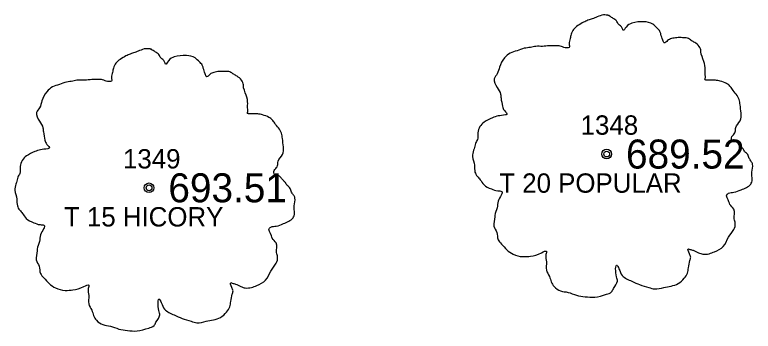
# Model space of a CAD drawing. Extents: x 1655137 to 1657928, y 1003994 to 1005407.
# Drawn here: x 1655879.78 to 1655917.99, y 1004697.34 to 1004713.71 of the extents above; entities that cross this region are included whole.
import ezdxf

# ---------------------------------------------------------------- set-up
doc = ezdxf.new("R2010")
doc.units = 0
for name, color, linetype in [('RD_EX_TX_VEG_ELEV', 7, 'Continuous'), ('RD_EX_VEG', 7, 'Continuous'), ('RD_EX_VEG_txCode', 7, 'Continuous'), ('RD_SMD_Locator', 7, 'Continuous')]:
    doc.layers.add(name, color=color, linetype=linetype)

msp = doc.modelspace()

# ---------------------------------------------------------------- linework, layer by layer
at = {"layer": 'RD_EX_VEG'}
for centre, radius in [((1655910.407, 1004706.504), 0.25), ((1655910.394, 1004706.486), 0.0001), ((1655886.725, 1004704.759), 0.25), ((1655886.712, 1004704.74), 0.0001)]:
    msp.add_circle(centre, radius, dxfattribs=at)
for points in [[(1655910.539, 1004713.672), (1655910.239, 1004713.697), (1655909.914, 1004713.597), (1655909.664, 1004713.497), (1655909.439, 1004713.422), (1655909.214, 1004713.322), (1655908.914, 1004713.147), (1655908.689, 1004712.947), (1655908.564, 1004712.697), (1655908.514, 1004712.472), (1655908.464, 1004712.197), (1655908.464, 1004712.022), (1655908.34, 1004711.997), (1655908.19, 1004712.022), (1655907.94, 1004712.097), (1655907.69, 1004712.097), (1655907.44, 1004712.097), (1655907.09, 1004712.072), (1655906.74, 1004712.072), (1655906.465, 1004712.022), (1655906.14, 1004711.972), (1655905.766, 1004711.847), (1655905.416, 1004711.722), (1655905.116, 1004711.473), (1655904.866, 1004710.998), (1655904.741, 1004710.648), (1655904.591, 1004710.398), (1655904.741, 1004709.948), (1655904.916, 1004709.598), (1655904.941, 1004709.398), (1655905.016, 1004708.974), (1655905.116, 1004708.749), (1655905.241, 1004708.549), (1655905.166, 1004708.524), (1655904.791, 1004708.474), (1655904.491, 1004708.374), (1655904.066, 1004708.149), (1655903.841, 1004707.924), (1655903.741, 1004707.599), (1655903.717, 1004707.249), (1655903.617, 1004707.05), (1655903.542, 1004706.775), (1655903.517, 1004706.7), (1655903.467, 1004706.375), (1655903.567, 1004705.925), (1655903.592, 1004705.575), (1655903.717, 1004705.35), (1655903.866, 1004705.175), (1655904.041, 1004704.925), (1655904.441, 1004704.701), (1655904.766, 1004704.601), (1655904.966, 1004704.576), (1655904.791, 1004704.076), (1655904.741, 1004703.726), (1655904.616, 1004703.326), (1655904.616, 1004703.251), (1655904.566, 1004702.776), (1655904.716, 1004702.451), (1655904.791, 1004702.077), (1655904.966, 1004701.852), (1655905.241, 1004701.552), (1655905.566, 1004701.327), (1655906.066, 1004701.202), (1655906.465, 1004701.227), (1655907.04, 1004701.402), (1655907.29, 1004701.477), (1655907.265, 1004701.302), (1655907.29, 1004700.927), (1655907.29, 1004700.502), (1655907.44, 1004700.178), (1655907.54, 1004699.903), (1655907.69, 1004699.653), (1655908.015, 1004699.428), (1655908.414, 1004699.353), (1655908.839, 1004699.203), (1655909.289, 1004699.128), (1655909.789, 1004699.103), (1655910.389, 1004699.253), (1655910.663, 1004699.378), (1655910.763, 1004699.553), (1655910.963, 1004699.928), (1655910.913, 1004700.153), (1655910.938, 1004700.752), (1655911.038, 1004700.577), (1655911.213, 1004700.227), (1655911.713, 1004699.928), (1655912.113, 1004699.753), (1655912.588, 1004699.603), (1655912.888, 1004699.528), (1655913.362, 1004699.603), (1655913.737, 1004699.678), (1655914.112, 1004699.803), (1655914.412, 1004700.078), (1655914.587, 1004700.352), (1655914.637, 1004700.627), (1655914.712, 1004701.002), (1655914.762, 1004701.177)], [(1655914.762, 1004701.177), (1655914.687, 1004701.352), (1655914.637, 1004701.602), (1655914.712, 1004701.577), (1655914.887, 1004701.527), (1655915.162, 1004701.402), (1655915.386, 1004701.327), (1655915.711, 1004701.352), (1655915.986, 1004701.452), (1655916.436, 1004701.727), (1655916.711, 1004702.202), (1655916.986, 1004702.601), (1655917.061, 1004702.926), (1655917.011, 1004703.151), (1655916.986, 1004703.651), (1655916.786, 1004703.901), (1655916.736, 1004704.026), (1655916.636, 1004704.426), (1655916.711, 1004704.476), (1655916.986, 1004704.526), (1655917.361, 1004704.651), (1655917.635, 1004704.775), (1655917.86, 1004704.95), (1655917.935, 1004705.175), (1655917.91, 1004705.575), (1655917.96, 1004705.975), (1655917.885, 1004706.125), (1655917.785, 1004706.275), (1655917.71, 1004706.475), (1655917.56, 1004706.625), (1655917.461, 1004706.775), (1655917.361, 1004706.875), (1655917.236, 1004707.025), (1655917.061, 1004707.149), (1655916.911, 1004707.199), (1655916.861, 1004707.349), (1655917.011, 1004707.549), (1655917.061, 1004707.649), (1655917.086, 1004707.874), (1655917.311, 1004708.224), (1655917.361, 1004708.624), (1655917.311, 1004709.049), (1655917.261, 1004709.324), (1655917.111, 1004709.598), (1655916.911, 1004709.848), (1655916.786, 1004710.023), (1655916.611, 1004710.148), (1655916.286, 1004710.273), (1655916.036, 1004710.323), (1655915.686, 1004710.323), (1655915.486, 1004710.373), (1655915.511, 1004710.423), (1655915.511, 1004710.573), (1655915.511, 1004710.848), (1655915.436, 1004711.298), (1655915.286, 1004711.797), (1655915.286, 1004711.822), (1655915.186, 1004712.072), (1655914.962, 1004712.272), (1655914.787, 1004712.372), (1655914.587, 1004712.497), (1655914.337, 1004712.522), (1655914.037, 1004712.522), (1655913.762, 1004712.472), (1655913.562, 1004712.372), (1655913.387, 1004712.247), (1655913.312, 1004712.397), (1655913.212, 1004712.697), (1655913.162, 1004712.847), (1655913.012, 1004713.022), (1655912.788, 1004713.222), (1655912.338, 1004713.347), (1655911.713, 1004713.272), (1655911.413, 1004713.072), (1655911.263, 1004712.897), (1655911.213, 1004713.022), (1655911.013, 1004713.222), (1655910.913, 1004713.397), (1655910.738, 1004713.522), (1655910.589, 1004713.622), (1655910.489, 1004713.672)], [(1655886.857, 1004711.926), (1655886.557, 1004711.951), (1655886.232, 1004711.851), (1655885.982, 1004711.751), (1655885.757, 1004711.676), (1655885.532, 1004711.576), (1655885.232, 1004711.401), (1655885.007, 1004711.201), (1655884.882, 1004710.952), (1655884.832, 1004710.727), (1655884.783, 1004710.452), (1655884.783, 1004710.277), (1655884.658, 1004710.252), (1655884.508, 1004710.277), (1655884.258, 1004710.352), (1655884.008, 1004710.352), (1655883.758, 1004710.352), (1655883.408, 1004710.327), (1655883.058, 1004710.327), (1655882.783, 1004710.277), (1655882.459, 1004710.227), (1655882.084, 1004710.102), (1655881.734, 1004709.977), (1655881.434, 1004709.727), (1655881.184, 1004709.252), (1655881.059, 1004708.902), (1655880.909, 1004708.653), (1655881.059, 1004708.203), (1655881.234, 1004707.853), (1655881.259, 1004707.653), (1655881.334, 1004707.228), (1655881.434, 1004707.003), (1655881.559, 1004706.803), (1655881.484, 1004706.778), (1655881.109, 1004706.728), (1655880.809, 1004706.628), (1655880.384, 1004706.404), (1655880.16, 1004706.179), (1655880.06, 1004705.854), (1655880.035, 1004705.504), (1655879.935, 1004705.304), (1655879.86, 1004705.029), (1655879.835, 1004704.954), (1655879.785, 1004704.629), (1655879.885, 1004704.179), (1655879.91, 1004703.83), (1655880.035, 1004703.605), (1655880.185, 1004703.43), (1655880.359, 1004703.18), (1655880.759, 1004702.955), (1655881.084, 1004702.855), (1655881.284, 1004702.83), (1655881.109, 1004702.33), (1655881.059, 1004701.98), (1655880.934, 1004701.581), (1655880.934, 1004701.506), (1655880.884, 1004701.031), (1655881.034, 1004700.706), (1655881.109, 1004700.331), (1655881.284, 1004700.106), (1655881.559, 1004699.806), (1655881.884, 1004699.582), (1655882.384, 1004699.457), (1655882.783, 1004699.482), (1655883.358, 1004699.656), (1655883.608, 1004699.731), (1655883.583, 1004699.557), (1655883.608, 1004699.182), (1655883.608, 1004698.757), (1655883.758, 1004698.432), (1655883.858, 1004698.157), (1655884.008, 1004697.907), (1655884.333, 1004697.682), (1655884.733, 1004697.607), (1655885.157, 1004697.457), (1655885.607, 1004697.382), (1655886.107, 1004697.357), (1655886.707, 1004697.507), (1655886.982, 1004697.632), (1655887.082, 1004697.807), (1655887.281, 1004698.182), (1655887.231, 1004698.407), (1655887.256, 1004699.007), (1655887.356, 1004698.832), (1655887.531, 1004698.482), (1655888.031, 1004698.182), (1655888.431, 1004698.007), (1655888.906, 1004697.857), (1655889.206, 1004697.782), (1655889.68, 1004697.857), (1655890.055, 1004697.932), (1655890.43, 1004698.057), (1655890.73, 1004698.332), (1655890.905, 1004698.607), (1655890.955, 1004698.882), (1655891.03, 1004699.257), (1655891.08, 1004699.432)], [(1655891.08, 1004699.432), (1655891.005, 1004699.607), (1655890.955, 1004699.856), (1655891.03, 1004699.831), (1655891.205, 1004699.781), (1655891.48, 1004699.656), (1655891.705, 1004699.582), (1655892.029, 1004699.607), (1655892.304, 1004699.706), (1655892.754, 1004699.981), (1655893.029, 1004700.456), (1655893.304, 1004700.856), (1655893.379, 1004701.181), (1655893.329, 1004701.406), (1655893.304, 1004701.905), (1655893.104, 1004702.155), (1655893.054, 1004702.28), (1655892.954, 1004702.68), (1655893.029, 1004702.73), (1655893.304, 1004702.78), (1655893.679, 1004702.905), (1655893.954, 1004703.03), (1655894.178, 1004703.205), (1655894.253, 1004703.43), (1655894.228, 1004703.83), (1655894.278, 1004704.229), (1655894.203, 1004704.379), (1655894.103, 1004704.529), (1655894.028, 1004704.729), (1655893.879, 1004704.879), (1655893.779, 1004705.029), (1655893.679, 1004705.129), (1655893.554, 1004705.279), (1655893.379, 1004705.404), (1655893.229, 1004705.454), (1655893.179, 1004705.604), (1655893.329, 1004705.804), (1655893.379, 1004705.904), (1655893.404, 1004706.129), (1655893.629, 1004706.478), (1655893.679, 1004706.878), (1655893.629, 1004707.303), (1655893.579, 1004707.578), (1655893.429, 1004707.853), (1655893.229, 1004708.103), (1655893.104, 1004708.278), (1655892.929, 1004708.403), (1655892.604, 1004708.528), (1655892.354, 1004708.578), (1655892.004, 1004708.578), (1655891.804, 1004708.628), (1655891.829, 1004708.678), (1655891.829, 1004708.827), (1655891.829, 1004709.102), (1655891.754, 1004709.552), (1655891.605, 1004710.052), (1655891.605, 1004710.077), (1655891.505, 1004710.327), (1655891.28, 1004710.527), (1655891.105, 1004710.627), (1655890.905, 1004710.752), (1655890.655, 1004710.777), (1655890.355, 1004710.777), (1655890.08, 1004710.727), (1655889.88, 1004710.627), (1655889.705, 1004710.502), (1655889.63, 1004710.652), (1655889.53, 1004710.952), (1655889.48, 1004711.101), (1655889.331, 1004711.276), (1655889.106, 1004711.476), (1655888.656, 1004711.601), (1655888.031, 1004711.526), (1655887.731, 1004711.326), (1655887.581, 1004711.151), (1655887.531, 1004711.276), (1655887.331, 1004711.476), (1655887.231, 1004711.651), (1655887.057, 1004711.776), (1655886.907, 1004711.876), (1655886.807, 1004711.926)]]:
    msp.add_spline(points, degree=3, dxfattribs=at)
at = {"layer": 'RD_SMD_Locator'}
for centre in [(1655910.407, 1004706.504), (1655886.725, 1004704.759)]:
    msp.add_circle(centre, 0.15, dxfattribs=at)

# ---------------------------------------------------------------- texts
at = {"layer": 'RD_EX_TX_VEG_ELEV'}
for s, p in [('689.52', (1655911.407, 1004705.754)), ('693.51', (1655887.725, 1004704.009))]:
    msp.add_text(s, height=1.5, dxfattribs=at).set_placement(p)
at = {"layer": 'RD_EX_VEG_txCode'}
for s, p in [('1348', (1655909.06, 1004707.504)), ('1349', (1655885.378, 1004705.759)), ('T 20 POPULAR', (1655904.848, 1004704.504)), ('T 15 HICORY', (1655882.323, 1004702.759))]:
    msp.add_text(s, height=1, dxfattribs=at).set_placement(p)

doc.saveas('drawing.dxf')
